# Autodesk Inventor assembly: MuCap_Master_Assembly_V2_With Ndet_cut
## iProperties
Shininess: 64.0
Length Units: 11269
Angle Units: 11279
Time Units: 11290
Mass Units: 11283
Length Display Precision: 3
Angle Display Precision: 2
Compacted: True
Created: 2004-08
Part Number: MuCap_Master_Assembly_V2_With Ndet_cut
Document SubType Name: Assembly
Designer: John Blackburn
Manufacturer: Standard
Standards Organization: Custom
Density: 0.0
Volumn: 0.0
Area: 0.0
PropertySet Name: Model Information
Control State: 0
Master: False
Checked Out: False
Author: John Blackburn
